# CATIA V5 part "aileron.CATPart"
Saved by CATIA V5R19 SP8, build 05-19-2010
Part number: aileron
Publications: "Largeur aileron"
Bounding box of the stored display mesh (mm): x -71 to 49, y -250 to 250, z 122 to 183
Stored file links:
  G:\EU_thinkMotion\CFAO_2010\MMS_groupe1\MMS_groupe1\A reprendre\OK\glenerrant\glenerrant\glenerrant\aileron.CATPart
  C:\Users\Gauthier\Documents\IFMA\Projet CFAO\LENERRANT\Systeme.CATProduct
  G:\EU_thinkMotion\CFAO_2010\MMS_groupe1\MMS_groupe1\A reprendre\OK\glenerrant\glenerrant\glenerrant\Squelette de base.CATPart
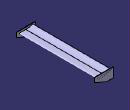
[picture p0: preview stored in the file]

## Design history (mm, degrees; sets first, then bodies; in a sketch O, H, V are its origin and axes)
Parameters
  `Largeur aileron` = 248 mm
Set1
  Point1: linked copy from another document
Set2
  Point2: (-9, -51, 147)
  Point3: (5, -51, 154)
  Point4: (-9, 51, 147)
  Point5: (5, 51, 154)
  Line1: type PtPt, FirstPoint Point2, SecondPoint Point4
  Line2: type PtPt, FirstPoint Point3, SecondPoint Point5
  Plane1: type Normal, Curve Line1, RefPoint Point2
  Plane2: type Normal, Curve Line1, RefPoint Point4
  Plane3: type Normal, Curve Line2, RefPoint Point3
  Plane4: type Normal, Curve Line2, RefPoint Point5
  Plane5: type Offset, RefPlane Plane1, Offset 3
  Plane6: type Offset, RefPlane Plane3, Offset 3
  Plane7: type Offset, RefPlane Plane2, Offset 3, reversed
  Plane8: type Offset, RefPlane Plane4, Offset 3, reversed
  Point6: (-58, 0, 175)
  Point7: (-56, 0, 172)
  Point8: (-56, 0, 176)
  Point9: (28, 0, 170)
  Point10: (31, 0, 166)
  Point11: (28, 0, 161)
  Point12: (-10, 0, 170)
  Point13: (-15, 0, 163)
  Plane9: type Offset, RefPlane Plane1, Offset 197 {= `Largeur aileron` -0.051}, reversed
  Plane10: type Offset, RefPlane Plane4, Offset 197 {= `Largeur aileron` -0.051}
Body1 (main body)
  Sketch1 on Plane7, origin (0, 48, 0), H (-1, 0, 0), V (0, 0, 1)
    arc A1 centre (9, 147) radius 1.5 from (8.3724, 145.6376) to (10.3624, 146.3724) ccw
    point P1 (9, 147)
    reference projected point E1 (9, 147) from Point4
    arc A2 centre (-5, 154) radius 2 from (-7, 154) to (-5.8368, 152.1835) ccw
    point P2 (-5, 154)
    reference projected point E2 (-5, 154) from Point5
    line L1 (8.3724, 145.6376) -> (-5.8368, 152.1835)
    line L2 (10.3624, 146.3724) -> (16.7905, 160.3259)
    line L3 (-7, 154) -> (-7, 161)
    line L4 (16.7905, 160.3259) -> (19.2905, 160.3259)
    line L5 (19.2905, 160.3259) -> (19.2905, 164.3259)
    line L6 (19.2905, 164.3259) -> (-7, 161)
    radius A1 = 1.5
    radius A2 = 2
    length L4 = 2.5
    length L5 = 4
    length L3 = 7
    length L6 = 26.5
    coincidence: E1 P1, P2 E2
    vertical: L3 V, L5 V
    horizontal: L4 H
    tangency: L2 A1, L1 A1, L1 A2, L3 A2
    perpendicularity: L2 L1
  Pad1: profile Sketch1, direction (0, -1, 0), length 2
  Sketch2 on Plane8, origin (0, 48, 0), H (-1, 0, 0), V (0, 0, 1)
    circle A1 centre (9, 147) radius 1.5
    point P1 (9, 147)
    circle A2 centre (-5, 154) radius 2
    point P2 (-5, 154)
    reference projected point E1 (9, 147) from Point4
    reference projected point E2 (-5, 154) from Point5
    radius A2 = 2
    radius A1 = 1.5
    coincidence: P1 E1, P2 E2
  Pad2: profile Sketch2, direction (0, 1, 0), length 6
  LineCorner1: Elements (Point11; Point10; Point9; Point12; Point8; Point6; Point7; Point13)
  Curve1: Elements (Point12; Point6; Point13; Point10), SemiClosure Point6
  Fill1: Boundary Curve1
  Pad3: profile Curve1, length 248 {= `Largeur aileron`}, mirrored extent
  Sketch3 on Plane9, origin (0, -248, 0), H (-1, 0, 0), V (0, 0, 1)
    line L1 (71, 183) -> (-49, 183)
    point P1 (71, 183)
    point P2 (-49, 183)
    line L2 (28, 122) -> (-49, 154.9996)
    point P3 (28, 122)
    point P4 (-49, 154.9996)
    line L3 (-49, 183) -> (-49, 154.9996)
    point P5 (-49, 183)
    point P6 (-49, 154.9996)
    line L4 (28, 122) -> (71, 122)
    point P7 (28, 122)
    point P8 (71, 122)
    line L5 (71, 122) -> (71, 183)
    point P9 (71, 122)
    point P10 (71, 183)
    reference projected point E1 (-5, 154) from Point3
    reference projected point E2 (-5, 154) from Point3
    distance L3 E1 = 44
    length L4 = 43
    length L5 = 61
    length L1 = 120
    length L3 = 28.0004
    distance L1 E2 = 29
    coincidence: P9 P8, P10 P1, P2 P5, P3 P7, P4 P6
    perpendicularity: L5 L4, L1 L5, L3 L1
    horizontal: L4 H
  Pad4: profile Sketch3, direction (0, -1, 0), length 2
  Sketch4 on Plane10, origin (0, 248, 0), H (-1, 0, 0), V (0, 0, 1)
    line L1 (71, 183) -> (-49, 183)
    point P1 (71, 183)
    point P2 (-49, 183)
    line L2 (71, 183) -> (71, 122)
    point P3 (71, 183)
    point P4 (71, 122)
    line L3 (71, 122) -> (28, 122)
    point P5 (71, 122)
    point P6 (28, 122)
    line L4 (28, 122) -> (-49, 155)
    point P7 (28, 122)
    point P8 (-49, 155)
    line L5 (-49, 155) -> (-49, 183)
    point P9 (-49, 155)
    point P10 (-49, 183)
    reference projected point E1 (-5, 154) from Point3
    reference projected point E2 (-5, 154) from Point3
    distance E1 L5 = 44
    distance E2 L1 = 29
    length L2 = 61
    length L5 = 28
    length L1 = 120
    length L3 = 43
    coincidence: P10 P2, P1 P3, P5 P4, P7 P6, P8 P9
    perpendicularity: L2 L3, L1 L2, L1 L5
    horizontal: L1 H
  Pad5: profile Sketch4, direction (0, 1, 0), length 2
  Sketch5 on Plane6, origin (0, -48, 0), H (-1, 0, 0), V (0, 0, 1)
    circle A1 centre (-5, 154) radius 2
    point P1 (-5, 154)
    circle A2 centre (9, 147) radius 1.5
    point P2 (9, 147)
    reference projected point E1 (-5, 154) from Point3
    reference projected point E2 (9, 147) from Point4
    radius A2 = 1.5
    radius A1 = 2
    coincidence: P1 E1, P2 E2
  Pad6: profile Sketch5, direction (0, -1, 0), length 6
  Sketch6 on Plane6, origin (0, -48, 0), H (-1, 0, 0), V (0, 0, 1)
    arc A1 centre (-5, 154) radius 2 from (-7, 154) to (-5.8368, 152.1835) ccw
    point P1 (-5, 154)
    arc A2 centre (9, 147) radius 1.5 from (8.3724, 145.6376) to (10.3624, 146.3724) ccw
    point P2 (9, 147)
    reference projected point E1 (-5, 154) from Point3
    reference projected point E2 (9, 147) from Point2
    line L1 (-7, 154) -> (-7, 161)
    point P4 (-7, 161)
    line L2 (-7, 161) -> (19.2905, 164.3259)
    point P5 (-7, 161)
    point P6 (19.2905, 164.3259)
    line L3 (19.2905, 164.3259) -> (19.2905, 160.3259)
    point P7 (19.2905, 164.3259)
    line L4 (19.2905, 160.3259) -> (16.7905, 160.3259)
    line L5 (16.7905, 160.3259) -> (10.3624, 146.3724)
    line L6 (8.3724, 145.6376) -> (-5.8368, 152.1835)
    radius A2 = 1.5
    radius A1 = 2
    length L2 = 26.5
    length L3 = 4
    length L4 = 2.5
    length L1 = 7
    coincidence: P1 E1, P2 E2, P5 L1, P7 P6, P4 P5
    tangency: L6 A2, L6 A1, L1 A1, L5 A2
    perpendicularity: L4 L3, L6 L5
    vertical: L3 V, L1 V
  Pad7: profile Sketch6, direction (0, 1, 0), length 2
